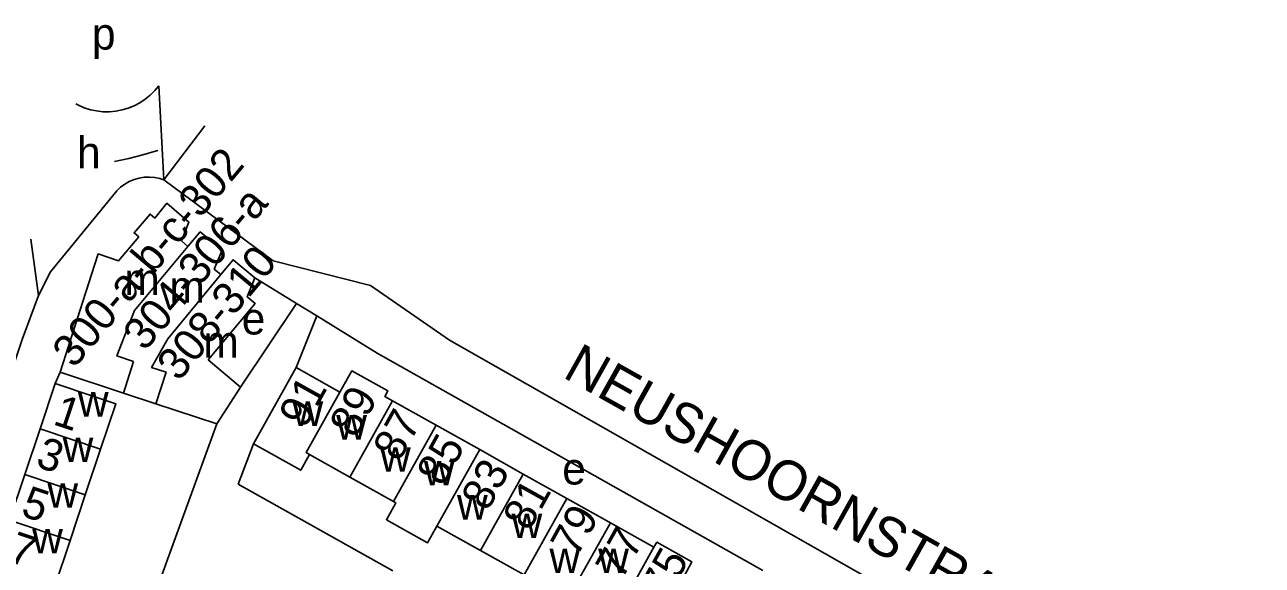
# Model space of a CAD drawing. Extents: x 162667 to 164645, y 379003 to 382150.
# Drawn here: x 163255.6 to 163411.5, y 381574.3 to 381642.4 of the extents above; entities that cross this region are included whole.
import ezdxf

# ---------------------------------------------------------------- set-up
doc = ezdxf.new("R2010")
doc.units = 0
for name, color, linetype in [('BLT_Basislijn', 7, 'Continuous'), ('BLT_Bebouwing', 7, 'Continuous'), ('BLT_Centroide', 7, 'Continuous'), ('BLT_Huisnummer', 7, 'Continuous'), ('BLT_Huisnummer_ tussenligend', 7, 'Continuous'), ('BLT_Huisnummer_reeks', 7, 'Continuous'), ('BLT_Onderverdeling_panden', 7, 'Continuous'), ('BLT_Straatnaam', 7, 'Continuous'), ('BLT_Vlakafsluiter', 7, 'Continuous')]:
    doc.layers.add(name, color=color, linetype=linetype)

msp = doc.modelspace()

# ---------------------------------------------------------------- linework, layer by layer
at = {"layer": 'BLT_Basislijn'}
for p, q in [((163271.38, 381633.52), (163271.96, 381634.09)), ((163271.96, 381634.09), (163272.46, 381634.7)), ((163262.03, 381632.42), (163262.34, 381632.25)), ((163262.34, 381632.25), (163263.08, 381631.93)), ((163268.62, 381631.88), (163269.37, 381632.19)), ((163269.37, 381632.19), (163270.09, 381632.57)), ((163270.09, 381632.57), (163270.76, 381633.01)), ((163270.76, 381633.01), (163271.38, 381633.52)), ((163263.08, 381631.93), (163263.85, 381631.69)), ((163263.85, 381631.69), (163264.64, 381631.53)), ((163264.64, 381631.53), (163265.44, 381631.44)), ((163265.44, 381631.44), (163266.25, 381631.43)), ((163266.25, 381631.43), (163267.06, 381631.5)), ((163267.06, 381631.5), (163267.85, 381631.66)), ((163267.85, 381631.66), (163268.62, 381631.88)), ((163289.83, 381607.3), (163284.59, 381610.51)), ((163309.1, 381602.67), (163299.16, 381609.56)), ((163282.79, 381596.77), (163289.83, 381607.3)), ((163292.39, 381605.72), (163289.83, 381607.3)), ((163292.39, 381605.72), (163289.8, 381599.21)), ((163309.1, 381602.67), (163350, 381579.47)), ((163260.03, 381598.66), (163259.43, 381597.22)), ((163301.96, 381573.62), (163282.48, 381584.56)), ((163350, 381579.47), (163411.54, 381544.56))]:
    msp.add_line(p, q, dxfattribs=at)
for points in [[(163266.91, 381625.18), (163268.69, 381625.55), (163270.46, 381625.99), (163272.2, 381626.51), (163272.34, 381626.56)], [(163267.17, 381621.47), (163267.65, 381621.92), (163268.18, 381622.32), (163268.75, 381622.65), (163269.36, 381622.9), (163270, 381623.08), (163270.65, 381623.18), (163271.31, 381623.21), (163271.97, 381623.15), (163272.62, 381623.01), (163273.11, 381622.85)], [(163273.11, 381622.85), (163286.9, 381612.67), (163299.16, 381609.56)], [(163267.17, 381621.47), (163258.81, 381611.29), (163257.31, 381608.31)], [(163257.31, 381608.31), (163255.25, 381602.77), (163232.11, 381532.97), (163224.48, 381509.21), (163221.33, 381500)], [(163348.58, 381573.67), (163300, 381601.05), (163292.39, 381605.72)], [(163279.8, 381592.12), (163267.15, 381557.4), (163254.01, 381516.05)], [(163282.48, 381584.56), (163284.43, 381589.61)]]:
    msp.add_lwpolyline(points, dxfattribs=at)
at = {"layer": 'BLT_Bebouwing'}
for p, q in [((163264.38, 381612.12), (163260.03, 381598.66)), ((163260.03, 381598.66), (163268.04, 381596.01)), ((163289.8, 381599.21), (163284.43, 381589.61)), ((163295.3, 381596.11), (163289.8, 381599.21)), ((163257.51, 381591.49), (163259.43, 381597.22)), ((163279.8, 381592.12), (163282.79, 381596.77)), ((163268.04, 381596.01), (163272.09, 381594.67)), ((163272.09, 381594.67), (163279.8, 381592.12)), ((163301.93, 381595.04), (163307.43, 381591.97)), ((163255.59, 381585.74), (163257.51, 381591.49)), ((163307.43, 381591.97), (163312.92, 381588.9)), ((163265.13, 381588.93), (163263.21, 381583.19)), ((163312.92, 381588.9), (163318.41, 381585.82)), ((163291.47, 381588.27), (163296.55, 381585.43)), ((163253.67, 381580), (163255.59, 381585.74)), ((163296.55, 381585.43), (163302.04, 381582.35)), ((163318.41, 381585.82), (163323.9, 381582.75)), ((163263.21, 381583.19), (163261.29, 381577.45)), ((163323.9, 381582.75), (163329.4, 381579.68)), ((163307.53, 381579.27), (163313.02, 381576.2)), ((163329.4, 381579.68), (163334.88, 381576.62)), ((163261.29, 381577.45), (163259.37, 381571.7)), ((163313.02, 381576.2), (163318.51, 381573.12))]:
    msp.add_line(p, q, dxfattribs=at)
for points in [[(163273.5, 381619.91), (163271.96, 381618.04), (163271.37, 381618.55), (163269.36, 381616.17), (163269.94, 381615.68), (163267.38, 381612.64), (163264.84, 381613.53), (163264.38, 381612.12)], [(163276.15, 381614.46), (163275.32, 381615.16), (163276.26, 381617.54), (163273.5, 381619.91)], [(163280.3, 381610.93), (163279.46, 381611.62), (163280.44, 381614.02), (163277.7, 381616.31), (163276.15, 381614.46)], [(163284.59, 381610.51), (163281.84, 381612.79), (163280.3, 381610.93)], [(163278.68, 381600.19), (163284.61, 381607.3), (163283.62, 381608.12), (163284.59, 381610.51)], [(163282.79, 381596.77), (163278.68, 381600.19)], [(163295.3, 381596.11), (163296.79, 381598.79), (163301.34, 381596.28), (163300.96, 381595.58), (163301.93, 381595.04)], [(163259.43, 381597.22), (163264.16, 381595.63), (163267.05, 381594.67), (163265.13, 381588.93)], [(163284.43, 381589.61), (163290.36, 381586.29), (163291.47, 381588.27)], [(163302.04, 381582.35), (163302.36, 381582.17), (163301.17, 381580.05), (163306.34, 381577.16), (163307.53, 381579.27)], [(163334.88, 381576.62), (163335.25, 381577.22), (163339.67, 381574.75), (163338.74, 381573.06), (163340, 381572.35)]]:
    msp.add_lwpolyline(points, dxfattribs=at)
at = {"layer": 'BLT_Onderverdeling_panden'}
for p, q in [((163280.3, 381610.93), (163273.61, 381602.86)), ((163269.27, 381600), (163268.04, 381596.01)), ((163296.55, 381585.43), (163301.93, 381595.04)), ((163265.13, 381588.93), (163257.51, 381591.49)), ((163307.43, 381591.97), (163302.04, 381582.35)), ((163307.53, 381579.27), (163312.92, 381588.9)), ((163263.21, 381583.19), (163255.59, 381585.74)), ((163318.41, 381585.82), (163313.02, 381576.2)), ((163318.51, 381573.12), (163323.9, 381582.75)), ((163261.29, 381577.45), (163253.67, 381580)), ((163329.4, 381579.68), (163323.99, 381570.04)), ((163334.88, 381576.62), (163329.48, 381566.97))]:
    msp.add_line(p, q, dxfattribs=at)
for points in [[(163276.15, 381614.46), (163269.4, 381606.42), (163267.19, 381600.68), (163269.27, 381600)], [(163272.09, 381594.67), (163273.4, 381598.64), (163271.57, 381599.24), (163273.61, 381602.86)], [(163295.3, 381596.11), (163291.06, 381588.51), (163291.47, 381588.27)]]:
    msp.add_lwpolyline(points, dxfattribs=at)
at = {"layer": 'BLT_Vlakafsluiter'}
for p, q in [((163272.47, 381634.69), (163273.11, 381622.85)), ((163278.28, 381629.67), (163273.11, 381622.85)), ((163256.36, 381615.4), (163257.31, 381608.31))]:
    msp.add_line(p, q, dxfattribs=at)

# ---------------------------------------------------------------- texts
at = {"layer": 'BLT_Centroide'}
for s, p in [('p', (163264.05, 381639.26)), ('h', (163262.17, 381624.3)), ('m', (163268.14, 381608.34)), ('m', (163273.81, 381607.39)), ('e', (163282.93, 381603.39)), ('m', (163278.09, 381600.48)), ('w', (163262.28, 381593.06)), ('w', (163289.32, 381591.88)), ('w', (163294.84, 381590.16)), ('w', (163260.36, 381587.34)), ('w', (163300.36, 381586.11)), ('w', (163305.88, 381584.39)), ('e', (163323.32, 381584.5)), ('w', (163258.44, 381581.59)), ('w', (163310.06, 381580.09)), ('w', (163316.93, 381577.76)), ('w', (163256.52, 381575.84)), ('w', (163321.71, 381573.34)), ('w', (163327.85, 381573.34))]:
    msp.add_text(s, height=4, dxfattribs=at).set_placement(p)
at = {"layer": 'BLT_Huisnummer'}
for s, rotation, p in [('91', 60.8628, (163290.89, 381591.43)), ('89', 60.8628, (163297.27, 381590.19)), ('1', 341.5042, (163259, 381592.12)), ('85', 60.8628, (163308.26, 381584.12)), ('5', 341.5042, (163254.94, 381580.62)), ('81', 60.8628, (163319.13, 381578.49)), ('77', 60.8628, (163330.81, 381572.36))]:
    msp.add_text(s, height=4, rotation=rotation, dxfattribs=at).set_placement(p)
at = {"layer": 'BLT_Huisnummer_ tussenligend'}
for s, rotation, p in [('87', 60.8628, (163302.75, 381587.22)), ('3', 341.5042, (163256.8, 381586.81)), ('83', 60.8628, (163313.88, 381580.99)), ('79', 60.8628, (163325.14, 381575.24)), ('7', 341.5042, (163253.31, 381574.87))]:
    msp.add_text(s, height=4, rotation=rotation, dxfattribs=at).set_placement(p)
at = {"layer": 'BLT_Huisnummer_reeks'}
for s, rotation, p in [('300-a-b-c-302', 49.9218, (163261.8, 381599.01)), ('304-306-a', 49.9218, (163270.72, 381601.16)), ('308-310', 50.1722, (163274.99, 381597.35)), ('73-75', 60.8628, (163332.69, 381563.06))]:
    msp.add_text(s, height=4, rotation=rotation, dxfattribs=at).set_placement(p)
at = {"layer": 'BLT_Straatnaam'}
msp.add_text('NEUSHOORNSTRAAT', height=5, rotation=330.752, dxfattribs=at).set_placement((163323.23, 381598.08))

doc.saveas('drawing.dxf')
